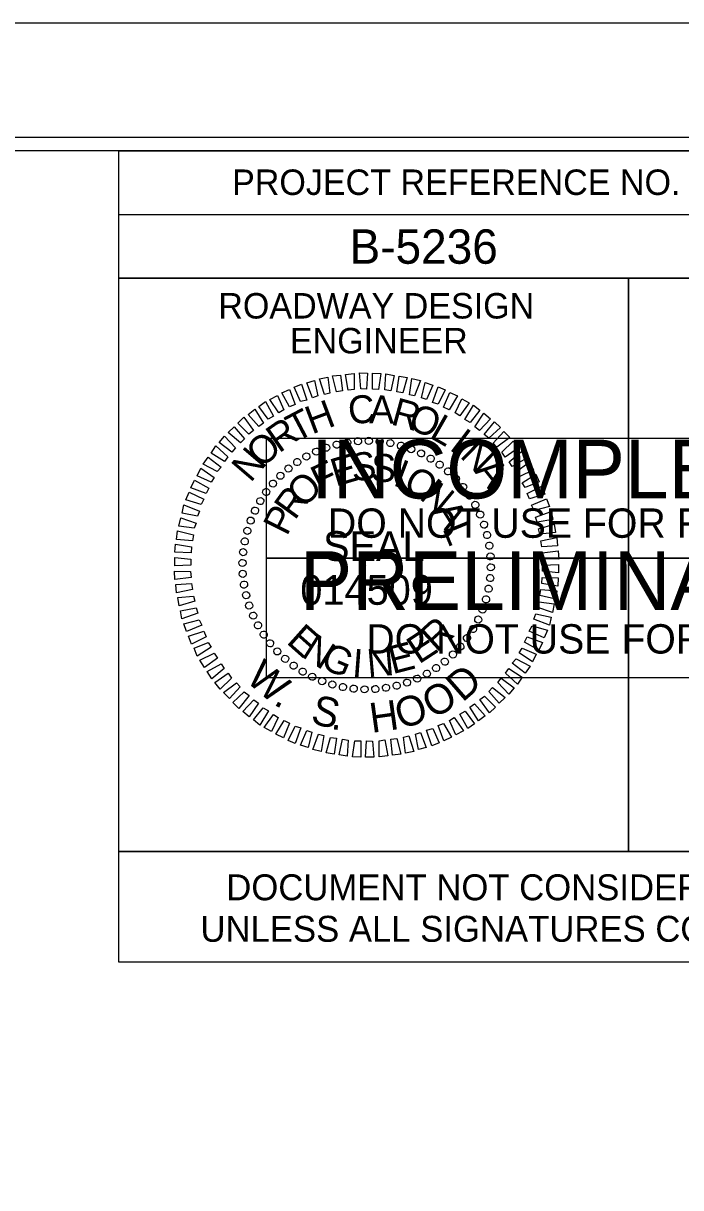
# Model space of a CAD drawing. Extents: x 1734085 to 1734267, y 541107 to 541226.
# Drawn here: x 1734241.04 to 1734254.98, y 541201.19 to 541225.88 of the extents above; entities that cross this region are included whole.
import ezdxf

# ---------------------------------------------------------------- set-up
doc = ezdxf.new("R2010")
doc.units = 0
for name, color, linetype in [('Sheet Cutting Line CELL', 7, 'Continuous'), ('Sheet Data Field CELL', 7, 'Continuous'), ('Sheet PE Seal Cell', 7, 'Continuous'), ('Sheet Plot Border Inside CELL', 7, 'Continuous'), ('Sheet Plot Border Outside CELL', 7, 'Continuous'), ('Sheet Sticker Exception Certification CELL', 7, 'Continuous'), ('Sheet Sticker Incomplete CELL', 7, 'Continuous'), ('Sheet Sticker Preliminary CELL', 7, 'Continuous'), ('Sheet Typical CELL', 7, 'Continuous'), ('Typical Detail Wedge2 CELL', 7, 'Continuous')]:
    doc.layers.add(name, color=color, linetype=linetype)

msp = doc.modelspace()

# ---------------------------------------------------------------- linework, layer by layer
at = {"layer": 'Sheet Cutting Line CELL'}
msp.add_line((1734266.513, 541225.875), (1734084.641, 541225.875), dxfattribs=at)
at = {"layer": 'Sheet PE Seal Cell'}
for p, q in [((1734247.462, 541216.884), (1734247.462, 541216.884)), ((1734247.682, 541216.947), (1734247.682, 541216.947)), ((1734247.913, 541216.989), (1734247.913, 541216.989)), ((1734248.139, 541217.02), (1734248.139, 541217.02)), ((1734248.37, 541217.025), (1734248.37, 541217.025)), ((1734248.601, 541217.01), (1734248.601, 541217.01)), ((1734248.827, 541216.973), (1734248.827, 541216.973)), ((1734249.047, 541216.926), (1734249.047, 541216.926)), ((1734247.047, 541216.695), (1734247.047, 541216.695)), ((1734247.252, 541216.8), (1734247.252, 541216.8)), ((1734249.268, 541216.852), (1734249.268, 541216.852)), ((1734249.478, 541216.758), (1734249.478, 541216.758)), ((1734249.683, 541216.653), (1734249.683, 541216.653)), ((1734246.664, 541216.443), (1734246.664, 541216.443)), ((1734246.848, 541216.574), (1734246.848, 541216.574)), ((1734249.872, 541216.521), (1734249.872, 541216.521)), ((1734250.055, 541216.38), (1734250.055, 541216.38)), ((1734246.333, 541216.122), (1734246.333, 541216.122)), ((1734246.491, 541216.285), (1734246.491, 541216.285)), ((1734250.218, 541216.222), (1734250.218, 541216.222)), ((1734246.191, 541215.939), (1734246.191, 541215.939)), ((1734250.376, 541216.049), (1734250.376, 541216.049)), ((1734246.06, 541215.75), (1734246.06, 541215.75)), ((1734250.507, 541215.865), (1734250.507, 541215.865)), ((1734250.628, 541215.666), (1734250.628, 541215.666)), ((1734245.955, 541215.545), (1734245.955, 541215.545)), ((1734250.733, 541215.461), (1734250.733, 541215.461)), ((1734245.861, 541215.335), (1734245.861, 541215.335)), ((1734250.817, 541215.251), (1734250.817, 541215.251)), ((1734245.74, 541214.894), (1734245.74, 541214.894)), ((1734245.787, 541215.114), (1734245.787, 541215.114)), ((1734250.88, 541215.03), (1734250.88, 541215.03)), ((1734245.703, 541214.668), (1734245.703, 541214.668)), ((1734250.922, 541214.799), (1734250.922, 541214.799)), ((1734245.687, 541214.437), (1734245.687, 541214.437)), ((1734250.953, 541214.574), (1734250.953, 541214.574)), ((1734245.693, 541214.206), (1734245.693, 541214.206)), ((1734248.323, 541214.39), (1734248.323, 541214.39)), ((1734250.958, 541214.343), (1734250.958, 541214.343)), ((1734245.724, 541213.98), (1734245.724, 541213.98)), ((1734250.943, 541214.112), (1734250.943, 541214.112)), ((1734245.766, 541213.749), (1734245.766, 541213.749)), ((1734250.859, 541213.665), (1734250.859, 541213.665)), ((1734250.906, 541213.886), (1734250.906, 541213.886)), ((1734245.829, 541213.529), (1734245.829, 541213.529)), ((1734250.785, 541213.445), (1734250.785, 541213.445)), ((1734245.913, 541213.319), (1734245.913, 541213.319)), ((1734250.691, 541213.235), (1734250.691, 541213.235)), ((1734246.018, 541213.114), (1734246.018, 541213.114)), ((1734246.139, 541212.915), (1734246.139, 541212.915)), ((1734250.586, 541213.03), (1734250.586, 541213.03)), ((1734246.27, 541212.731), (1734246.27, 541212.731)), ((1734250.454, 541212.841), (1734250.454, 541212.841)), ((1734246.428, 541212.558), (1734246.428, 541212.558)), ((1734250.155, 541212.495), (1734250.155, 541212.495)), ((1734250.313, 541212.657), (1734250.313, 541212.657)), ((1734246.59, 541212.4), (1734246.59, 541212.4)), ((1734246.774, 541212.258), (1734246.774, 541212.258)), ((1734249.798, 541212.206), (1734249.798, 541212.206)), ((1734249.982, 541212.337), (1734249.982, 541212.337)), ((1734246.963, 541212.127), (1734246.963, 541212.127)), ((1734247.168, 541212.022), (1734247.168, 541212.022)), ((1734247.378, 541211.928), (1734247.378, 541211.928)), ((1734249.394, 541211.98), (1734249.394, 541211.98)), ((1734249.599, 541212.085), (1734249.599, 541212.085)), ((1734247.598, 541211.854), (1734247.598, 541211.854)), ((1734247.819, 541211.807), (1734247.819, 541211.807)), ((1734248.045, 541211.77), (1734248.045, 541211.77)), ((1734248.276, 541211.754), (1734248.276, 541211.754)), ((1734248.507, 541211.76), (1734248.507, 541211.76)), ((1734248.732, 541211.791), (1734248.732, 541211.791)), ((1734248.963, 541211.833), (1734248.963, 541211.833)), ((1734249.184, 541211.896), (1734249.184, 541211.896))]:
    msp.add_line(p, q, dxfattribs=at)
for points in [[(1734247.43, 541218.007), (1734247.32, 541218.338), (1734247.499, 541218.375), (1734247.541, 541218.033)], [(1734247.682, 541218.065), (1734247.598, 541218.401), (1734247.772, 541218.417), (1734247.808, 541218.081)], [(1734247.934, 541218.096), (1734247.877, 541218.432), (1734248.055, 541218.453), (1734248.06, 541218.112)], [(1734248.197, 541218.123), (1734248.171, 541218.464), (1734248.344, 541218.459), (1734248.323, 541218.117)], [(1734248.449, 541218.117), (1734248.449, 541218.459), (1734248.622, 541218.453), (1734248.575, 541218.112)], [(1734248.711, 541218.102), (1734248.732, 541218.443), (1734248.906, 541218.411), (1734248.837, 541218.081)], [(1734248.963, 541218.06), (1734249.011, 541218.396), (1734249.184, 541218.369), (1734249.089, 541218.044)], [(1734249.231, 541218.002), (1734249.284, 541218.343), (1734249.462, 541218.301), (1734249.341, 541217.976)], [(1734246.69, 541217.745), (1734246.522, 541218.039), (1734246.685, 541218.112), (1734246.806, 541217.792)], [(1734246.921, 541217.855), (1734246.785, 541218.159), (1734246.942, 541218.222), (1734247.052, 541217.886)], [(1734247.178, 541217.939), (1734247.058, 541218.254), (1734247.22, 541218.301), (1734247.289, 541217.976)], [(1734249.483, 541217.934), (1734249.562, 541218.259), (1734249.725, 541218.207), (1734249.593, 541217.897)], [(1734249.719, 541217.839), (1734249.84, 541218.17), (1734249.987, 541218.107), (1734249.84, 541217.802)], [(1734246.233, 541217.487), (1734246.039, 541217.755), (1734246.176, 541217.855), (1734246.349, 541217.55)], [(1734246.464, 541217.619), (1734246.27, 541217.902), (1734246.433, 541217.986), (1734246.564, 541217.682)], [(1734249.956, 541217.739), (1734250.087, 541218.049), (1734250.25, 541217.976), (1734250.071, 541217.682)], [(1734250.197, 541217.619), (1734250.339, 541217.918), (1734250.496, 541217.829), (1734250.297, 541217.556)], [(1734246.034, 541217.33), (1734245.808, 541217.582), (1734245.95, 541217.692), (1734246.134, 541217.398)], [(1734250.402, 541217.477), (1734250.586, 541217.781), (1734250.722, 541217.671), (1734250.517, 541217.414)], [(1734250.617, 541217.319), (1734250.811, 541217.608), (1734250.948, 541217.493), (1734250.717, 541217.246)], [(1734245.824, 541217.167), (1734245.593, 541217.398), (1734245.719, 541217.524), (1734245.924, 541217.241)], [(1734250.817, 541217.157), (1734251.032, 541217.43), (1734251.158, 541217.304), (1734250.916, 541217.078)], [(1734245.467, 541216.784), (1734245.194, 541216.989), (1734245.309, 541217.125), (1734245.54, 541216.878)], [(1734245.651, 541216.983), (1734245.383, 541217.199), (1734245.514, 541217.319), (1734245.735, 541217.067)], [(1734251.006, 541216.973), (1734251.231, 541217.22), (1734251.357, 541217.094), (1734251.084, 541216.889)], [(1734245.309, 541216.584), (1734245.026, 541216.763), (1734245.126, 541216.915), (1734245.378, 541216.684)], [(1734251.189, 541216.784), (1734251.431, 541217.02), (1734251.541, 541216.878), (1734251.263, 541216.679)], [(1734245.152, 541216.374), (1734244.858, 541216.532), (1734244.963, 541216.679), (1734245.236, 541216.469)], [(1734251.347, 541216.579), (1734251.604, 541216.8), (1734251.704, 541216.647), (1734251.41, 541216.479)], [(1734245.026, 541216.149), (1734244.727, 541216.28), (1734244.805, 541216.443), (1734245.089, 541216.248)], [(1734251.483, 541216.364), (1734251.762, 541216.563), (1734251.861, 541216.406), (1734251.557, 541216.259)], [(1734244.921, 541215.907), (1734244.595, 541216.028), (1734244.674, 541216.191), (1734244.973, 541216.023)], [(1734251.62, 541216.133), (1734251.914, 541216.317), (1734251.982, 541216.154), (1734251.683, 541216.033)], [(1734244.816, 541215.676), (1734244.49, 541215.771), (1734244.559, 541215.933), (1734244.874, 541215.786)], [(1734251.725, 541215.907), (1734252.035, 541216.065), (1734252.103, 541215.897), (1734251.777, 541215.792)], [(1734244.737, 541215.424), (1734244.412, 541215.492), (1734244.448, 541215.666), (1734244.779, 541215.534)], [(1734251.819, 541215.66), (1734252.14, 541215.797), (1734252.197, 541215.634), (1734251.872, 541215.55)], [(1734244.669, 541215.172), (1734244.343, 541215.214), (1734244.38, 541215.393), (1734244.711, 541215.282)], [(1734251.903, 541215.408), (1734252.239, 541215.529), (1734252.271, 541215.356), (1734251.94, 541215.298)], [(1734251.966, 541215.156), (1734252.297, 541215.256), (1734252.329, 541215.078), (1734251.998, 541215.046)], [(1734244.627, 541214.904), (1734244.291, 541214.936), (1734244.312, 541215.114), (1734244.653, 541215.03)], [(1734252.014, 541214.904), (1734252.355, 541214.978), (1734252.371, 541214.799), (1734252.035, 541214.778)], [(1734244.601, 541214.652), (1734244.259, 541214.663), (1734244.27, 541214.836), (1734244.611, 541214.778)], [(1734252.045, 541214.652), (1734252.386, 541214.694), (1734252.397, 541214.516), (1734252.056, 541214.526)], [(1734244.595, 541214.39), (1734244.254, 541214.374), (1734244.254, 541214.553), (1734244.595, 541214.516)], [(1734252.05, 541214.39), (1734252.392, 541214.406), (1734252.392, 541214.227), (1734252.05, 541214.264)], [(1734244.601, 541214.127), (1734244.259, 541214.085), (1734244.249, 541214.264), (1734244.59, 541214.253)], [(1734244.632, 541213.875), (1734244.291, 541213.802), (1734244.275, 541213.98), (1734244.611, 541214.001)], [(1734252.045, 541214.127), (1734252.386, 541214.117), (1734252.376, 541213.944), (1734252.035, 541214.001)], [(1734244.679, 541213.623), (1734244.349, 541213.524), (1734244.317, 541213.702), (1734244.648, 541213.734)], [(1734252.019, 541213.875), (1734252.355, 541213.844), (1734252.334, 541213.665), (1734251.993, 541213.749)], [(1734244.742, 541213.371), (1734244.406, 541213.251), (1734244.375, 541213.424), (1734244.706, 541213.482)], [(1734251.977, 541213.608), (1734252.302, 541213.566), (1734252.266, 541213.387), (1734251.935, 541213.497)], [(1734244.826, 541213.119), (1734244.506, 541212.983), (1734244.448, 541213.146), (1734244.774, 541213.23)], [(1734251.909, 541213.356), (1734252.234, 541213.287), (1734252.197, 541213.114), (1734251.867, 541213.245)], [(1734244.921, 541212.873), (1734244.611, 541212.715), (1734244.543, 541212.883), (1734244.868, 541212.988)], [(1734251.83, 541213.104), (1734252.155, 541213.009), (1734252.087, 541212.846), (1734251.772, 541212.993)], [(1734245.026, 541212.647), (1734244.732, 541212.463), (1734244.664, 541212.626), (1734244.963, 541212.747)], [(1734251.725, 541212.873), (1734252.05, 541212.752), (1734251.972, 541212.589), (1734251.672, 541212.757)], [(1734245.162, 541212.416), (1734244.884, 541212.216), (1734244.784, 541212.374), (1734245.089, 541212.521)], [(1734251.62, 541212.631), (1734251.919, 541212.5), (1734251.84, 541212.337), (1734251.557, 541212.531)], [(1734245.299, 541212.201), (1734245.042, 541211.98), (1734244.942, 541212.132), (1734245.236, 541212.3)], [(1734251.336, 541212.195), (1734251.62, 541212.017), (1734251.52, 541211.865), (1734251.268, 541212.096)], [(1734251.494, 541212.405), (1734251.788, 541212.248), (1734251.683, 541212.101), (1734251.41, 541212.311)], [(1734245.456, 541211.996), (1734245.215, 541211.76), (1734245.105, 541211.901), (1734245.383, 541212.101)], [(1734251.179, 541211.996), (1734251.452, 541211.791), (1734251.336, 541211.655), (1734251.105, 541211.901)], [(1734245.64, 541211.807), (1734245.414, 541211.56), (1734245.288, 541211.686), (1734245.561, 541211.891)], [(1734245.829, 541211.623), (1734245.614, 541211.35), (1734245.488, 541211.476), (1734245.729, 541211.702)], [(1734250.995, 541211.796), (1734251.263, 541211.581), (1734251.132, 541211.46), (1734250.911, 541211.712)], [(1734246.029, 541211.46), (1734245.834, 541211.172), (1734245.698, 541211.287), (1734245.929, 541211.534)], [(1734250.612, 541211.45), (1734250.838, 541211.198), (1734250.696, 541211.088), (1734250.512, 541211.382)], [(1734250.822, 541211.613), (1734251.053, 541211.382), (1734250.927, 541211.256), (1734250.722, 541211.539)], [(1734246.244, 541211.303), (1734246.06, 541210.998), (1734245.924, 541211.109), (1734246.128, 541211.366)], [(1734246.449, 541211.161), (1734246.307, 541210.862), (1734246.149, 541210.951), (1734246.349, 541211.224)], [(1734250.412, 541211.292), (1734250.607, 541211.025), (1734250.47, 541210.925), (1734250.297, 541211.229)], [(1734246.69, 541211.04), (1734246.559, 541210.731), (1734246.396, 541210.804), (1734246.575, 541211.098)], [(1734246.926, 541210.941), (1734246.806, 541210.61), (1734246.659, 541210.673), (1734246.806, 541210.977)], [(1734249.956, 541211.035), (1734250.124, 541210.741), (1734249.961, 541210.668), (1734249.84, 541210.988)], [(1734250.181, 541211.161), (1734250.376, 541210.878), (1734250.213, 541210.794), (1734250.082, 541211.098)], [(1734247.163, 541210.846), (1734247.084, 541210.521), (1734246.921, 541210.573), (1734247.052, 541210.883)], [(1734247.415, 541210.778), (1734247.362, 541210.437), (1734247.184, 541210.479), (1734247.304, 541210.804)], [(1734247.682, 541210.72), (1734247.635, 541210.384), (1734247.462, 541210.41), (1734247.556, 541210.736)], [(1734247.934, 541210.678), (1734247.913, 541210.337), (1734247.74, 541210.368), (1734247.808, 541210.699)], [(1734248.963, 541210.715), (1734249.047, 541210.379), (1734248.874, 541210.363), (1734248.837, 541210.699)], [(1734249.215, 541210.773), (1734249.326, 541210.442), (1734249.147, 541210.405), (1734249.105, 541210.746)], [(1734249.467, 541210.841), (1734249.588, 541210.526), (1734249.425, 541210.479), (1734249.357, 541210.804)], [(1734249.725, 541210.925), (1734249.861, 541210.62), (1734249.704, 541210.557), (1734249.593, 541210.893)], [(1734248.197, 541210.662), (1734248.197, 541210.321), (1734248.024, 541210.326), (1734248.071, 541210.668)], [(1734248.449, 541210.657), (1734248.475, 541210.316), (1734248.302, 541210.321), (1734248.323, 541210.662)], [(1734248.711, 541210.683), (1734248.769, 541210.347), (1734248.591, 541210.326), (1734248.585, 541210.668)]]:
    msp.add_lwpolyline(points, close=True, dxfattribs=at)
for centre, major_axis in [((1734247.252, 541216.796), (-0.0307, 0.0691)), ((1734247.466, 541216.88), (-0.0246, 0.0715)), ((1734247.686, 541216.945), (-0.0183, 0.0734)), ((1734247.911, 541216.991), (-0.0118, 0.0747)), ((1734248.139, 541217.017), (-0.0053, 0.0754)), ((1734248.369, 541217.023), (0.0013, 0.0756)), ((1734248.598, 541217.009), (0.0079, 0.0752)), ((1734248.825, 541216.975), (0.0144, 0.0742)), ((1734249.049, 541216.921), (0.0208, 0.0727)), ((1734249.267, 541216.848), (0.0271, 0.0706)), ((1734246.85, 541216.573), (-0.0423, 0.0627)), ((1734247.046, 541216.693), (-0.0367, 0.0661)), ((1734249.477, 541216.757), (0.0331, 0.0679)), ((1734249.679, 541216.647), (0.0389, 0.0648)), ((1734246.494, 541216.284), (-0.0525, 0.0544)), ((1734246.666, 541216.437), (-0.0476, 0.0588)), ((1734249.871, 541216.52), (0.0444, 0.0612)), ((1734250.051, 541216.377), (0.0496, 0.0571)), ((1734246.335, 541216.118), (-0.0571, 0.0496)), ((1734250.217, 541216.219), (0.0544, 0.0525)), ((1734250.369, 541216.047), (0.0588, 0.0476)), ((1734246.192, 541215.938), (-0.0612, 0.0444)), ((1734250.506, 541215.863), (0.0627, 0.0423)), ((1734245.956, 541215.544), (-0.0679, 0.0331)), ((1734246.066, 541215.746), (-0.0648, 0.0389)), ((1734250.626, 541215.667), (0.0661, 0.0367)), ((1734245.864, 541215.334), (-0.0706, 0.0271)), ((1734250.729, 541215.461), (0.0691, 0.0307)), ((1734245.791, 541215.116), (-0.0727, 0.0208)), ((1734250.813, 541215.247), (0.0715, 0.0246)), ((1734245.738, 541214.892), (-0.0742, 0.0144)), ((1734250.878, 541215.027), (0.0734, 0.0183)), ((1734245.704, 541214.665), (-0.0752, 0.0079)), ((1734250.924, 541214.802), (0.0747, 0.0118)), ((1734250.95, 541214.574), (0.0754, 0.0053)), ((1734245.69, 541214.436), (-0.0756, 0.0013)), ((1734250.956, 541214.344), (0.0756, -0.0013)), ((1734245.696, 541214.206), (-0.0754, -0.0053)), ((1734250.942, 541214.115), (0.0752, -0.0079)), ((1734245.722, 541213.978), (-0.0747, -0.0118)), ((1734250.908, 541213.888), (0.0742, -0.0144)), ((1734245.768, 541213.753), (-0.0734, -0.0183)), ((1734250.854, 541213.664), (0.0727, -0.0208)), ((1734245.833, 541213.533), (-0.0715, -0.0246)), ((1734250.781, 541213.446), (0.0706, -0.0271)), ((1734245.917, 541213.319), (-0.0691, -0.0307)), ((1734246.02, 541213.113), (-0.0661, -0.0367)), ((1734250.69, 541213.236), (0.0679, -0.0331)), ((1734246.14, 541212.917), (-0.0627, -0.0423)), ((1734250.453, 541212.842), (0.0612, -0.0444)), ((1734250.58, 541213.034), (0.0648, -0.0389)), ((1734246.276, 541212.733), (-0.0588, -0.0476)), ((1734250.31, 541212.662), (0.0571, -0.0496)), ((1734246.429, 541212.561), (-0.0544, -0.0525)), ((1734246.595, 541212.403), (-0.0496, -0.0571)), ((1734249.98, 541212.343), (0.0476, -0.0588)), ((1734250.152, 541212.496), (0.0525, -0.0544)), ((1734246.775, 541212.26), (-0.0444, -0.0612)), ((1734246.967, 541212.133), (-0.0389, -0.0648)), ((1734249.6, 541212.087), (0.0367, -0.0661)), ((1734249.795, 541212.207), (0.0423, -0.0627)), ((1734247.168, 541212.023), (-0.0331, -0.0679)), ((1734247.379, 541211.931), (-0.0271, -0.0706)), ((1734247.597, 541211.859), (-0.0208, -0.0727)), ((1734249.18, 541211.9), (0.0246, -0.0715)), ((1734249.394, 541211.984), (0.0307, -0.0691)), ((1734247.82, 541211.805), (-0.0144, -0.0742)), ((1734248.048, 541211.771), (-0.0079, -0.0752)), ((1734248.277, 541211.757), (-0.0013, -0.0756)), ((1734248.507, 541211.763), (0.0053, -0.0754)), ((1734248.735, 541211.789), (0.0118, -0.0747)), ((1734248.96, 541211.835), (0.0183, -0.0734))]:
    msp.add_ellipse(centre, major_axis=major_axis, ratio=0.999708, dxfattribs=at)
at = {"layer": 'Sheet Plot Border Inside CELL'}
msp.add_lwpolyline([(1734266.027, 541223.451), (1734086.045, 541223.451), (1734086.045, 541109.5), (1734266.027, 541109.5)], close=True, dxfattribs=at)
at = {"layer": 'Sheet Plot Border Outside CELL'}
msp.add_lwpolyline([(1734266.513, 541225.875), (1734084.641, 541225.875), (1734084.641, 541107.075), (1734266.513, 541107.075)], close=True, dxfattribs=at)
at = {"layer": 'Sheet Sticker Exception Certification CELL'}
for p, q in [((1734243.071, 541205.97), (1734243.071, 541208.32)), ((1734243.071, 541208.32), (1734264.677, 541208.32)), ((1734264.677, 541205.97), (1734243.071, 541205.97))]:
    msp.add_line(p, q, dxfattribs=at)
at = {"layer": 'Sheet Sticker Incomplete CELL'}
msp.add_lwpolyline([(1734246.196, 541214.54), (1734246.196, 541217.078), (1734262.072, 541217.078), (1734262.072, 541214.54)], close=True, dxfattribs=at)
at = {"layer": 'Sheet Sticker Preliminary CELL'}
msp.add_lwpolyline([(1734246.196, 541212.002), (1734246.196, 541214.54), (1734262.072, 541214.54), (1734262.072, 541212.002)], close=True, dxfattribs=at)
at = {"layer": 'Sheet Typical CELL'}
for p, q in [((1734243.071, 541221.82), (1734264.677, 541221.82)), ((1734253.877, 541220.47), (1734253.877, 541208.325))]:
    msp.add_line(p, q, dxfattribs=at)
for points in [[(1734264.677, 541223.175), (1734102.677, 541223.175), (1734102.677, 541109.775), (1734264.677, 541109.775)], [(1734243.071, 541223.175), (1734264.677, 541223.175), (1734264.677, 541220.47), (1734243.071, 541220.47)], [(1734243.071, 541220.47), (1734253.877, 541220.47), (1734253.877, 541208.32), (1734243.071, 541208.32)], [(1734253.877, 541220.47), (1734264.677, 541220.47), (1734264.677, 541208.32), (1734253.877, 541208.32)]]:
    msp.add_lwpolyline(points, close=True, dxfattribs=at)

# ---------------------------------------------------------------- texts
at = {"layer": 'Sheet Data Field CELL'}
msp.add_text('B-5236', height=0.729, dxfattribs=at).set_placement((1734247.961, 541220.778))
at = {"layer": 'Sheet PE Seal Cell'}
for s, height, rotation, p in [('H', 0.592, 20.6195, (1734247.163, 541217.157)), ('C', 0.592, 6.2199, (1734247.961, 541217.367)), ('A', 0.592, 359.0203, (1734248.375, 541217.398)), ('R', 0.592, 344.6211, (1734248.816, 541217.377)), ('T', 0.592, 27.8198, (1734246.821, 541216.983)), ('O', 0.592, 337.4212, (1734249.168, 541217.298)), ('R', 0.592, 35.0205, (1734246.464, 541216.752)), ('L', 0.592, 330.2209, (1734249.63, 541217.104)), ('O', 0.592, 42.2217, (1734246.102, 541216.427)), ('I', 0.592, 323.0201, (1734250.055, 541216.852)), ('N', 0.592, 49.4235, (1734245.861, 541216.122)), ('N', 0.592, 315.8189, (1734250.281, 541216.689)), ('F', 0.592, 25.967, (1734247.331, 541215.891)), ('E', 0.592, 16.6111, (1734247.667, 541216.049)), ('S', 0.592, 7.2556, (1734248.029, 541216.159)), ('S', 0.592, 357.9004, (1734248.407, 541216.164)), ('I', 0.592, 339.1896, (1734248.858, 541216.091)), ('O', 0.592, 329.8335, (1734249.068, 541216.017)), ('A', 0.592, 308.6172, (1734250.591, 541216.38)), ('O', 0.592, 44.6812, (1734246.984, 541215.582)), ('N', 0.592, 320.4766, (1734249.42, 541215.807)), ('R', 0.592, 54.0397, (1734246.8, 541215.324)), ('P', 0.592, 63.3989, (1734246.632, 541214.988)), ('A', 0.592, 301.7603, (1734249.719, 541215.534)), ('L', 0.592, 292.4008, (1734249.924, 541215.172)), ('SEAL', 0.6298, 360, (1734247.399, 541214.479)), ('R', 0.592, 42.4814, (1734249.803, 541212.526)), ('E', 0.592, 318.2769, (1734246.601, 541212.747)), ('N', 0.592, 327.634, (1734246.916, 541212.463)), ('E', 0.592, 33.1241, (1734249.431, 541212.279)), ('G', 0.592, 336.9902, (1734247.315, 541212.227)), ('E', 0.592, 14.4118, (1734248.874, 541212.075)), ('I', 0.592, 355.7012, (1734248.003, 541212.027)), ('N', 0.592, 5.0564, (1734248.354, 541212.012))]:
    msp.add_text(s, height=height, rotation=rotation, dxfattribs=at).set_placement(p)
msp.add_text('014509', height=0.6298, dxfattribs=at).set_placement((1734246.917, 541213.549))
at = {"layer": 'Sheet Sticker Exception Certification CELL'}
for s, p in [('DOCUMENT NOT CONSIDERED FINAL', (1734245.347, 541207.285)), ('UNLESS ALL SIGNATURES COMPLETED', (1734244.799, 541206.405))]:
    msp.add_text(s, height=0.55, dxfattribs=at).set_placement(p)
at = {"layer": 'Sheet Sticker Incomplete CELL'}
for s, height, p in [('INCOMPLETE PLANS', 1.24416, (1734247.146, 541215.803)), ('DO NOT USE FOR R/W ACQUISITION', 0.62208, (1734247.502, 541214.969))]:
    msp.add_text(s, height=height, dxfattribs=at).set_placement(p)
at = {"layer": 'Sheet Sticker Preliminary CELL'}
for s, height, p in [('PRELIMINARY PLANS', 1.24416, (1734246.906, 541213.439)), ('DO NOT USE FOR CONSTRUCTION', 0.62208, (1734248.316, 541212.515))]:
    msp.add_text(s, height=height, dxfattribs=at).set_placement(p)
at = {"layer": 'Sheet Typical CELL'}
for s, height, p in [('PROJECT REFERENCE NO.', 0.54001, (1734245.469, 541222.236)), ('ROADWAY DESIGN', 0.54001, (1734245.177, 541219.617)), ('ENGINEER', 0.54, (1734246.695, 541218.877))]:
    msp.add_text(s, height=height, dxfattribs=at).set_placement(p)
at = {"layer": 'Typical Detail Wedge2 CELL'}
for s, rotation, p in [('W', 319.62, (1734245.736, 541211.945)), ('D', 41.0529, (1734250.355, 541211.467)), ('O', 29.4925, (1734249.728, 541211.119)), ('.', 332.1541, (1734246.328, 541211.442)), ('S', 346.3882, (1734247.114, 541211.042)), ('H', 7.9481, (1734248.429, 541210.832)), ('O', 17.9321, (1734249.044, 541210.904)), ('.', 353.7139, (1734247.551, 541210.915))]:
    msp.add_text(s, height=0.63, rotation=rotation, dxfattribs=at).set_placement(p)

doc.saveas('drawing.dxf')
